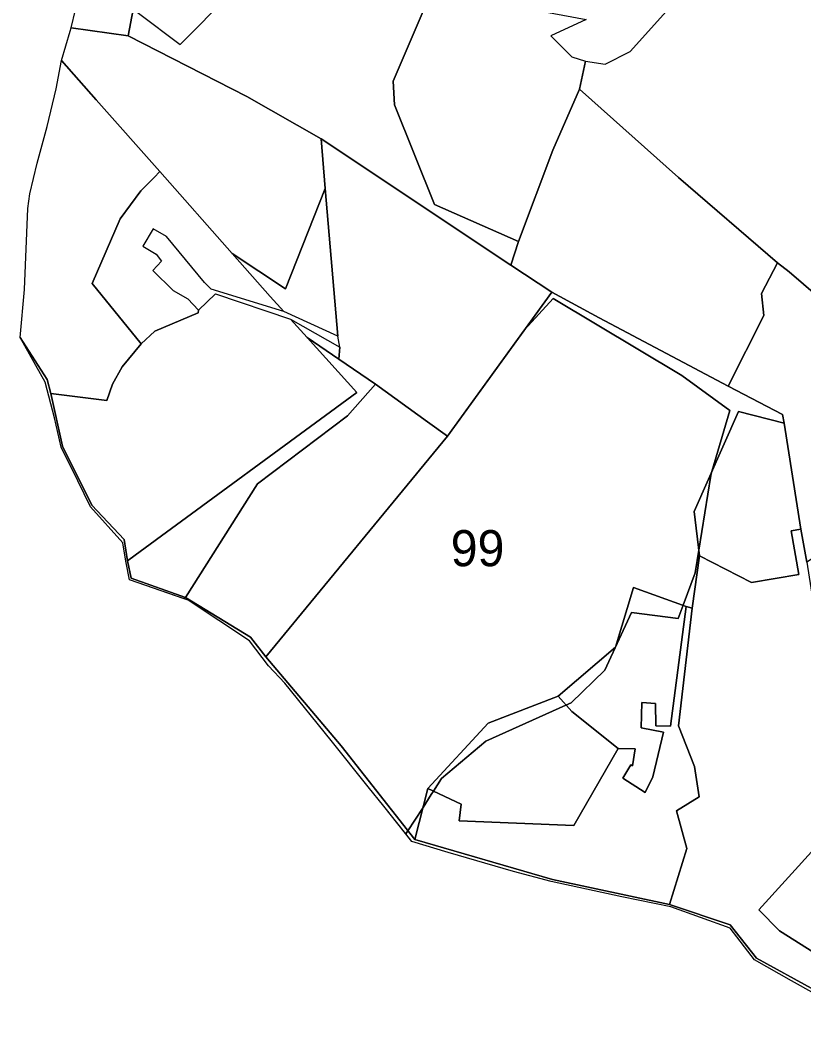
# Model space of a CAD drawing. Extents: x -477304 to -465429, y -1159113 to -1149210.
# Drawn here: x -477066.2 to -476740.3, y -1151359.6 to -1150940.8 of the extents above; entities that cross this region are included whole.
import ezdxf

# ---------------------------------------------------------------- set-up
doc = ezdxf.new("R2010")
doc.units = 0
for name, color, linetype in [('BPEJ_s', 7, 'Continuous'), ('orna_s', 7, 'Continuous'), ('PUPFL_s', 7, 'Continuous'), ('trav_porost_s', 7, 'Continuous'), ('voda_s', 7, 'Continuous')]:
    doc.layers.add(name, color=color, linetype=linetype)

msp = doc.modelspace()

# ---------------------------------------------------------------- linework, layer by layer
at = {"layer": 'BPEJ_s'}
for points in [[(-477020.82, -1151173.45), (-477022.27, -1151165.67), (-477023.58, -1151158.02), (-477037.03, -1151143.06), (-477042.28, -1151132.25), (-477049.2, -1151118.26), (-477051.97, -1151106.15), (-477055.89, -1151091.29), (-477066.24, -1151072.69), (-477064.47, -1151052.72), (-477063.02, -1151019.12), (-477062.27, -1151012.97), (-477059.18, -1151000.19), (-477055.06, -1150984.99), (-477051.32, -1150969.33), (-477048.98, -1150957.57), (-477045.43, -1150945.42), (-477044.96, -1150943.97), (-477039.58, -1150921.4)], [(-476710.35, -1151359.62), (-476745.43, -1151340.08), (-476760.78, -1151331.42), (-476770.9, -1151318.15), (-476795.57, -1151309.38), (-476815.96, -1151305.15), (-476845.39, -1151298.8), (-476861.02, -1151294.62), (-476888.18, -1151286.78), (-476903.33, -1151282.11), (-476905.78, -1151279.04), (-476904.97, -1151277.77), (-476902.13, -1151273.35), (-476898.68, -1151267.98), (-476895.22, -1151262.58), (-476894.35, -1151261.22), (-476891, -1151256), (-476872.5, -1151240.5), (-476839.22, -1151225.5), (-476837, -1151224.5), (-476823, -1151211), (-476812, -1151187), (-476792.5, -1151189.5), (-476790.47, -1151183.99), (-476785.5, -1151170.5), (-476783.99, -1151161.08), (-476779, -1151130), (-476778.53, -1151128.4), (-476771, -1151103), (-476791, -1151088.5), (-476844.5, -1151056.5), (-476856.43, -1151069.51), (-476888.48, -1151113.75), (-476896.85, -1151107.69), (-476918.41, -1151092.06), (-476930.08, -1151105.21), (-476967.51, -1151133.52), (-476997.51, -1151180.8), (-476997.69, -1151180.74), (-476997.98, -1151181.33), (-477020.82, -1151173.45)]]:
    msp.add_lwpolyline(points, dxfattribs=at)
msp.add_lwpolyline([(-476771, -1151103), (-476778.53, -1151128.4), (-476779, -1151130), (-476783.99, -1151161.08), (-476785.5, -1151170.5), (-476790.47, -1151183.99), (-476792.5, -1151189.5), (-476812, -1151187), (-476823, -1151211), (-476837, -1151224.5), (-476839.22, -1151225.5), (-476872.5, -1151240.5), (-476891, -1151256), (-476894.35, -1151261.22), (-476895.22, -1151262.58), (-476898.68, -1151267.98), (-476902.13, -1151273.35), (-476904.97, -1151277.77), (-476905.78, -1151279.04), (-476914.98, -1151267.52), (-476921.51, -1151259.43), (-476936.94, -1151240.18), (-476956.09, -1151216.37), (-476962.92, -1151209.15), (-476970.8, -1151198.79), (-476996.4, -1151181.88), (-476997.98, -1151181.33), (-476997.69, -1151180.74), (-476997.51, -1151180.8), (-476967.51, -1151133.52), (-476930.08, -1151105.21), (-476918.41, -1151092.06), (-476896.85, -1151107.69), (-476888.48, -1151113.75), (-476856.43, -1151069.51), (-476844.5, -1151056.5), (-476791, -1151088.5)], close=True, dxfattribs=at)
at = {"layer": 'orna_s'}
msp.add_lwpolyline([(-477007.38, -1151041.03), (-477011.11, -1151044.88), (-477002.54, -1151053.18), (-476996.55, -1151056.65), (-476992.07, -1151061.3), (-476992.19, -1151062.42), (-477010.27, -1151070.07), (-477015.92, -1151075.38), (-477036.31, -1151050.29), (-477024.66, -1151023.35), (-477016.06, -1151011.76), (-477010.54, -1151006.18), (-477008.13, -1151003.75), (-476978.04, -1151037.78), (-476962.21, -1151055.69), (-476956.58, -1151061.94), (-476986.85, -1151052.63), (-476989.51, -1151049.87), (-477005.38, -1151030.78), (-477010.93, -1151027.5), (-477015.26, -1151034.82), (-477009.71, -1151038.1)], close=True, dxfattribs=at)
at = {"layer": 'PUPFL_s'}
for points in [[(-477044.96, -1150943.97), (-477039.58, -1150921.4), (-477019.17, -1150936.36), (-477021.36, -1150947.39)], [(-476875.56, -1150932.04), (-476830.86, -1150940.55), (-476845.5, -1150947.38), (-476836.72, -1150956.13), (-476831.04, -1150957.93), (-476833.59, -1150969.48), (-476844.74, -1150994.83), (-476858.92, -1151032.8), (-476893.87, -1151017.5), (-476910.55, -1150975.96), (-476911.05, -1150966.24), (-476893.99, -1150926.34)], [(-476833.59, -1150969.48), (-476792.37, -1151006.26), (-476751.24, -1151041.62), (-476757.9, -1151054.48), (-476756.97, -1151063.57), (-476771.78, -1151092.94), (-476825.35, -1151064.52), (-476845.08, -1151053.85), (-476862.21, -1151042.6), (-476858.92, -1151032.8), (-476844.74, -1150994.83)], [(-476749.12, -1151104.65), (-476771.78, -1151092.94), (-476756.97, -1151063.57), (-476757.9, -1151054.48), (-476751.24, -1151041.62), (-476746.44, -1151045.37), (-476663.71, -1151116.55), (-476739.03, -1151166.11), (-476741.53, -1151152.33), (-476748.54, -1151108.37)], [(-476785.9, -1151144.98), (-476783.7, -1151163.5), (-476786.72, -1151185.25), (-476789.2, -1151184.44), (-476811.2, -1151176.67), (-476818.65, -1151201.46), (-476842.51, -1151221.83), (-476871.58, -1151233.05), (-476896.68, -1151260.12), (-476902.11, -1151281.41), (-476932.77, -1151242.37), (-476964.08, -1151205.43), (-476888.48, -1151113.75), (-476845.08, -1151053.85), (-476825.35, -1151064.52), (-476771.78, -1151092.94), (-476749.12, -1151104.65), (-476748.54, -1151108.37), (-476767.43, -1151103.45)], [(-476970.48, -1151197.22), (-476997.51, -1151180.8), (-476967.51, -1151133.52), (-476930.08, -1151105.21), (-476918.41, -1151092.06), (-476896.85, -1151107.69), (-476888.48, -1151113.75), (-476964.08, -1151205.43)], [(-476742.31, -1151171.25), (-476762.01, -1151174.51), (-476783.7, -1151163.5), (-476785.9, -1151144.98), (-476767.43, -1151103.45), (-476748.54, -1151108.37), (-476741.53, -1151152.33), (-476745.53, -1151153.07)], [(-476783.7, -1151163.5), (-476762.01, -1151174.51), (-476742.31, -1151171.25), (-476745.53, -1151153.07), (-476741.53, -1151152.33), (-476739.03, -1151166.11), (-476733.64, -1151200.69), (-476678.03, -1151267.64), (-476701.48, -1151297.65), (-476735.66, -1151285.01), (-476759, -1151310.63), (-476750.46, -1151319.37), (-476728.26, -1151333.32), (-476735.68, -1151343.95), (-476760, -1151330.69), (-476770.97, -1151316.86), (-476796.2, -1151308.31), (-476788.91, -1151285.1), (-476793.24, -1151269.38), (-476783.77, -1151263.67), (-476785.71, -1151250.99), (-476792.45, -1151234.1), (-476786.72, -1151185.25)], [(-476789.2, -1151184.44), (-476795.74, -1151234.27), (-476801.83, -1151234.1), (-476801.94, -1151224.76), (-476807.71, -1151224.47), (-476807.88, -1151234.94), (-476798.63, -1151236.76), (-476803.05, -1151255.29), (-476806.25, -1151261.75), (-476815.51, -1151255.8), (-476812.31, -1151250.31), (-476811.54, -1151250.73), (-476810.39, -1151243.62), (-476817.51, -1151243.53), (-476836.8, -1151228.2), (-476842.51, -1151221.83), (-476818.65, -1151201.46), (-476811.2, -1151176.67)], [(-476783.77, -1151263.67), (-476793.24, -1151269.38), (-476788.91, -1151285.1), (-476796.2, -1151308.31), (-476844.88, -1151297.98), (-476902.11, -1151281.41), (-476896.68, -1151260.12), (-476882.87, -1151266.61), (-476883.64, -1151273.52), (-476835.95, -1151275.55), (-476817.51, -1151243.53), (-476810.39, -1151243.62), (-476811.54, -1151250.73), (-476812.31, -1151250.31), (-476815.51, -1151255.8), (-476806.25, -1151261.75), (-476803.05, -1151255.29), (-476798.63, -1151236.76), (-476807.88, -1151234.94), (-476807.71, -1151224.47), (-476801.94, -1151224.76), (-476801.83, -1151234.1), (-476795.74, -1151234.27), (-476789.2, -1151184.44), (-476786.72, -1151185.25), (-476792.45, -1151234.1), (-476785.71, -1151250.99)], [(-476882.87, -1151266.61), (-476896.68, -1151260.12), (-476871.58, -1151233.05), (-476842.51, -1151221.83), (-476836.8, -1151228.2), (-476817.51, -1151243.53), (-476835.95, -1151275.55), (-476883.64, -1151273.52)], [(-476728.26, -1151333.32), (-476750.46, -1151319.37), (-476759, -1151310.63), (-476735.66, -1151285.01), (-476701.48, -1151297.65)]]:
    msp.add_lwpolyline(points, close=True, dxfattribs=at)
msp.add_lwpolyline([(-476666.61, -1150937.08), (-476664.44, -1150949.33), (-476680.81, -1150942.03), (-476714.37, -1150989.57), (-476661.01, -1151024.56), (-476649.25, -1151018.99), (-476643, -1151051.19), (-476634.92, -1151088.51), (-476633.21, -1151098.11), (-476663.71, -1151116.55), (-476746.44, -1151045.37), (-476751.24, -1151041.62), (-476792.37, -1151006.26), (-476833.59, -1150969.48), (-476831.04, -1150957.93), (-476822.87, -1150959.17), (-476812.56, -1150953.81), (-476791.13, -1150930.01)], dxfattribs=at)
at = {"layer": 'trav_porost_s'}
for points in [[(-477021.36, -1150947.39), (-477019.17, -1150936.36), (-477017.07, -1150937.95), (-476999.7, -1150950.91), (-476958.1, -1150908.9), (-476923.69, -1150922.1), (-476893.99, -1150926.34), (-476911.05, -1150966.24), (-476910.55, -1150975.96), (-476893.87, -1151017.5), (-476858.92, -1151032.8), (-476862.21, -1151042.6), (-476941.07, -1150990.21), (-476971.89, -1150972.53)], [(-477008.13, -1151003.75), (-477034.56, -1150973.88), (-477048.98, -1150957.57), (-477045.43, -1150945.42), (-477044.96, -1150943.97), (-477021.36, -1150947.39), (-476971.89, -1150972.53), (-476941.07, -1150990.21), (-476939.31, -1151010.83), (-476955.83, -1151052.48), (-476978.04, -1151037.78)], [(-477053.52, -1151095.99), (-477055.05, -1151090.22), (-477066.24, -1151072.69), (-477064.47, -1151052.72), (-477063.02, -1151019.12), (-477062.27, -1151012.97), (-477059.18, -1151000.19), (-477055.06, -1150984.99), (-477051.32, -1150969.33), (-477048.98, -1150957.57), (-477034.56, -1150973.88), (-477008.13, -1151003.75), (-477010.54, -1151006.18), (-477016.06, -1151011.76), (-477024.66, -1151023.35), (-477036.31, -1151050.29), (-477015.92, -1151075.38), (-477023.82, -1151084.9), (-477027.86, -1151092.06), (-477030.25, -1151098.95)], [(-476934.06, -1151072.16), (-476939.31, -1151010.83), (-476941.07, -1150990.21), (-476862.21, -1151042.6), (-476845.08, -1151053.85), (-476888.48, -1151113.75), (-476896.85, -1151107.69), (-476918.41, -1151092.06), (-476933.7, -1151081.67), (-476933.25, -1151076.77)], [(-476939.31, -1151010.83), (-476934.06, -1151072.16), (-476956.58, -1151061.94), (-476962.21, -1151055.69), (-476978.04, -1151037.78), (-476955.83, -1151052.48)], [(-477015.92, -1151075.38), (-477010.27, -1151070.07), (-476992.19, -1151062.42), (-476992.07, -1151061.3), (-476985.03, -1151054.52), (-476953.75, -1151065.09), (-476946.85, -1151072.74), (-476926.22, -1151095.63), (-477018.4, -1151163.18), (-477021.55, -1151165.49), (-477022.96, -1151156.68), (-477036.37, -1151142.34), (-477048.62, -1151117.82), (-477053.52, -1151095.99), (-477030.25, -1151098.95), (-477027.86, -1151092.06), (-477023.82, -1151084.9)], [(-476933.25, -1151076.77), (-476933.7, -1151081.67), (-476946.85, -1151072.74), (-476953.75, -1151065.09)], [(-476933.7, -1151081.67), (-476918.41, -1151092.06), (-476930.08, -1151105.21), (-476967.51, -1151133.52), (-476997.51, -1151180.8), (-477020.02, -1151172.74), (-477021.55, -1151165.49), (-477018.4, -1151163.18), (-476926.22, -1151095.63), (-476946.85, -1151072.74)]]:
    msp.add_lwpolyline(points, close=True, dxfattribs=at)
at = {"layer": 'voda_s'}
msp.add_lwpolyline([(-476710.35, -1151359.62), (-476745.43, -1151340.08), (-476760.78, -1151331.42), (-476770.9, -1151318.15), (-476795.57, -1151309.38), (-476815.96, -1151305.15), (-476845.39, -1151298.8), (-476861.02, -1151294.62), (-476888.18, -1151286.78), (-476903.33, -1151282.11), (-476914.98, -1151267.52), (-476921.51, -1151259.43), (-476936.94, -1151240.18), (-476956.09, -1151216.37), (-476962.92, -1151209.15), (-476970.8, -1151198.79), (-476996.4, -1151181.88), (-477020.82, -1151173.45), (-477022.27, -1151165.67), (-477023.58, -1151158.02), (-477037.03, -1151143.06), (-477042.28, -1151132.25), (-477049.2, -1151118.26), (-477051.97, -1151106.15), (-477055.89, -1151091.29), (-477066.24, -1151072.69), (-477055.05, -1151090.22), (-477053.52, -1151095.99), (-477048.62, -1151117.82), (-477036.37, -1151142.34), (-477022.96, -1151156.68), (-477021.55, -1151165.49), (-477020.02, -1151172.74), (-476997.51, -1151180.8), (-476970.48, -1151197.22), (-476964.08, -1151205.43), (-476932.77, -1151242.37), (-476902.11, -1151281.41), (-476844.88, -1151297.98), (-476796.2, -1151308.31), (-476770.97, -1151316.86), (-476760, -1151330.69), (-476735.68, -1151343.95)], dxfattribs=at)

# ---------------------------------------------------------------- texts
at = {"layer": 'BPEJ_s'}
msp.add_text('99', height=15, dxfattribs=at).set_placement((-476887.15, -1151167.77))

doc.saveas('drawing.dxf')
